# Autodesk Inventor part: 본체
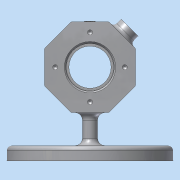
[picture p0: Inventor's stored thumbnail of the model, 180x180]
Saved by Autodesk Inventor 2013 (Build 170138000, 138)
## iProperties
Created: 2017-06
Part Number: 본체
Material: 알루미늄 6061
Document SubType Name: Modeling
Designer: dgall
Mass: 562.264 g
Surface Area: 566.116 cm^2
Volume: 207.477 cm^3
Density: 2.71 g/cm^3
Author: dgall
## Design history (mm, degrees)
sketch "스케치1"
  geometry: L1 (30, -12.426)-(12.426, -30); L2 (12.426, -30)-(-12.426, -30); L3 (-12.426, -30)-(-30, -12.426); L4 (-30, -12.426)-(-30, 12.426); L5 (-30, 12.426)-(-12.426, 30); L6 (-12.426, 30)-(12.426, 30); L7 (12.426, 30)-(30, 12.426); L8 (30, 12.426)-(30, -12.426); 3 further points
  constraints: 16 end point, 1 coincident, 1 midpoint, 1 vertical alignment, 17 other
  dimensions: "d0" = 60 distance between parallel lines of L2 L6
extrude "돌출1" new body sketch "스케치1" stored distance "d1" = 70; taper "d2" = 0 deg
sketch "스케치2"
  geometry: L1 (-35, 0)-(35, 0); L2 (-35, 16)-(-35, 30); L3 (-35, 30)-(35, 30); L4 (35, 30)-(35, 16); L5 (35, 16)-(23, 16); L6 (23, 16)-(23, 14); L7 (23, 14)-(20, 14); L8 (20, 14)-(20, 25); L9 (20, 25)-(-20, 25); L10 (-20, 25)-(-20, 14); L11 (-20, 14)-(-23, 14); L12 (-23, 14)-(-23, 16); L13 (-23, 16)-(-35, 16); L14 (-35, 16)-(-35, 0); L15 (-35, 0)-(35, 0); L16 (35, 0)-(35, 16); 2 further points
  constraints: 32 end point, 10 parallel, 4 perpendicular, 3 collinear, 2 coincident, 2 horizontal alignment, 2 vertical alignment, 1 horizontal, 1 midpoint
  dimensions: "d3" = 50 diameter of L9 L1; "d5" = 60 diameter of L3 L1; "d6" = 28 diameter of L11 L1; "d7" = 32 diameter of L13 L1; "d8" = 12 distance of L12.end L2.start; "d9" = 40 distance of L8.end L9.end; "d10" = 3 distance of L10.end L11.end
revolve "회전1" sketch "스케치2" stored, may be unused: angle "d11" = 90 deg
sketch "스케치3"
  geometry: C1 r 16 at (0, 0) reference; 1 further point
  constraints: 1 vertical alignment
  dimensions: "d13" = 23 distance of C1.centre point (0, 23)
hole "구멍1" sketch "스케치3" at (0, 23) diameter "d14" = 3.459; stored, may be unused: countersink angle "d18" = 90 deg, drill point angle "d20" = 118 deg; dims "d15" = 8, "d16" = 4, "d17" = 2, "d19" = 10
node "작업 평면1"
sketch "스케치4"
  geometry: C1 r 55 at (0, 0); 1 further point
  constraints: 1 centre point, 1 coincident
  dimensions: "d25" = 110 diameter of C1
extrude "돌출2" join sketch "스케치4" distance "d26" = 10; taper "d27" = 0 deg
sketch "스케치6"
  geometry: L1 (0, 0)-(0, 63.945); C1 r 55 at (0, 0) reference; A1 r 43 centre (0, 0) between (30.406, 30.406) and (-30.406, 30.406); A2 r 48 centre (0, 0) between (33.941, 33.941) and (-33.941, 33.941); A3 r 38 centre (0, 0) between (26.87, 26.87) and (-26.87, 26.87); A4 r 5 centre (-30.406, 30.406) between (-33.941, 33.941) and (-26.87, 26.87); A5 r 5 centre (30.406, 30.406) between (26.87, 26.87) and (33.941, 33.941); 3 further points
  constraints: 12 point on circle, 5 centre point, 4 tangent, 3 vertical alignment, 2 end point, 1 concentric, 1 horizontal alignment, 1 vertical
  dimensions: "d42" = 63.94496 distance of L1.start L1.end; "d43" = 43 radius of A1; "d44" = 5 radial gap between concentric circles of A1 A2; "d45" = 5 radial gap between concentric circles of A3 A1; "d46" = 30.40559 horizontal distance of L1.start A4.centre; "d47" = 30.40559 horizontal distance of L1.start A1.start; "d48" = 48 distance of L1.start point (0, 48)
extrude "돌출3" cut sketch "스케치6" distance "d49" = 3; taper "d50" = 0 deg
sketch "스케치7"
  geometry: A1 r 48 centre (0, 0) between (33.941, 33.941) and (-33.941, 33.941) reference; A2 r 5 centre (-30.406, 30.406) between (-33.941, 33.941) and (-26.87, 26.87) reference; A3 r 38 centre (0, 0) between (26.87, 26.87) and (-26.87, 26.87) reference; A4 r 5 centre (30.406, 30.406) between (26.87, 26.87) and (33.941, 33.941) reference; A5 r 48 centre (0, 0) between (33.941, 33.941) and (-33.941, 33.941) reference; A6 r 5 centre (-30.406, 30.406) between (-33.941, 33.941) and (-26.87, 26.87) reference; A7 r 38 centre (0, 0) between (26.87, 26.87) and (-26.87, 26.87) reference; A8 r 5 centre (30.406, 30.406) between (26.87, 26.87) and (33.941, 33.941) reference; A9 r 2 centre (-30.406, 30.406) between (-31.82, 31.82) and (-28.991, 28.991); A10 r 45 centre (0, 0) between (31.82, 31.82) and (-31.82, 31.82); A11 r 2 centre (30.406, 30.406) between (28.991, 28.991) and (31.82, 31.82); A12 r 41 centre (0, 0) between (28.991, 28.991) and (-28.991, 28.991)
  constraints: 8 point on circle, 4 centre point, 3 other
  dimensions: "d51" = 2 radius of A9
extrude "돌출4" cut sketch "스케치7" stored distance "d53" = 3; taper "d54" = 0 deg
sketch "스케치8"
  geometry: L1 (-24, 5)-(24, 5); L2 (24, -5)-(15.013, -5); L3 (15.013, -5)-(-24, -5); A1 r 38 centre (0, 0) between (-26.87, -26.87) and (26.87, -26.87) reference; A2 r 48 centre (0, 0) between (-33.941, -33.941) and (33.941, -33.941) reference; A3 r 5 centre (24, 0) between (24, -5) and (24, 5); A4 r 5 centre (-24, 0) between (-24, 5) and (-24, -5); 1 further point
  constraints: 6 end point, 4 point on circle, 4 tangent, 2 centre point, 1 equal radius, 1 horizontal, 1 horizontal alignment, 1 midpoint, 1 parallel, 1 vertical alignment
  dimensions: "d55" = 48 distance of A3.centre A4.centre; "d57" = 5 radius of A4
extrude "돌출5" join sketch "스케치8" stored distance "d58" = 3; taper "d59" = 0 deg
sketch "스케치10"
  geometry: L1 (0, 0)-(38.902, 0); L2 (12.426, 30)-(30, 12.426) reference; L3 (0, 0)-(21.213, 21.213); 1 further point
  constraints: 4 end point, 1 coincident, 1 horizontal, 1 midpoint, 1 perpendicular
  dimensions: "d62" = 38.90183 distance of L1.start L1.end
sketch "스케치11"
  geometry: C1 r 8 at (35, 12.426); 1 further point
  constraints: 1 centre point, 1 coincident
  dimensions: "d63" = 16 diameter of C1
extrude "돌출6" join sketch "스케치11" distance "d65" = 7; taper "d66" = 0 deg
sketch "스케치12"
  geometry: C1 r 8 at (0, 0) reference; 1 further point
  constraints: 1 coincident
hole "구멍2" sketch "스케치12" at (0, 0) diameter "d67" = 8; stored, may be unused: countersink angle "d71" = 90 deg, drill point angle "d73" = 118 deg; dims "d68" = 8, "d69" = 4, "d70" = 2, "d72" = 10
sketch "스케치13"
  geometry: L1 (70, 42.426)-(0, 42.426) reference; 2 further points
  constraints: 1 other
  dimensions: "d74" = 35 horizontal distance of point (35, 12.508) L1.end; "d75" = 30 vertical distance of point (35, 12.426) L1.end (derived)
extrude "돌출7" join sketch "스케치13" distance "d76" = 0.5; taper "d77" = 0 deg
fillet "모깎기2" dims "d78" = 5
fillet "모깎기3" dims "d79" = 3
fillet "모깎기4" dims "d80" = 3
fillet "모깎기5" dims "d81" = 0.3
chamfer "모따기1" distance "d82" = 1; stored, may be unused: second distance "d83" = 2, angle "d84" = 45 deg
chamfer "모따기2" distance "d85" = 1; stored, may be unused: second distance "d86" = 2, angle "d87" = 45 deg
fillet "모깎기6" dims "d88" = 1
node "솔리드1"
pattern_circular "원형 패턴1" dims angle "d22" = 360 deg
mirror "대칭1"
mirror "대칭2"
node "투영된 루프1"
other parameters: "d24" = -62
